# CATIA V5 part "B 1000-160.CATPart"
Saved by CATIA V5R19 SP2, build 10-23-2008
Part number: B 1000-160
Bounding box of the stored display mesh (mm): x -24.865 to 24.865, y -24.997 to 24.997, z 0 to 415
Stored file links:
  C:\Users\Bora\Desktop\3D Katı model\B serisi\B 1000\B 1000-160.CATPart
  C:\Program Files\Dassault Systemes\B19\intel_a\reffiles\standard\MetricThickPitch.txt
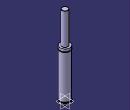
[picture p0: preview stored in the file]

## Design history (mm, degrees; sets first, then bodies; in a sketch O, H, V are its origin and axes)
Body1 (main body)
  Sketch1 on yz-plane, origin (0, 0, 0), H (0, 1, 0), V (0, 0, 1)
    point P1 (25, 239.5)
    point P2 (25, 235.5)
    point P3 (25, 239.5)
    point P6 (25, 235.5)
    point P9 (15, 414)
    point P11 (15, 414)
    arc A1 centre (25, 237.5) radius 2 from (25, 239.5) to (25, 235.5) ccw
    line L1 (25, 239.5) -> (25, 252)
    line L2 (25, 13) -> (25, 235.5)
    line L3 (21.5, 13) -> (21.5, 8)
    arc A2 centre (14, 414) radius 1 from (15, 414) to (14, 415) ccw
    line L4 (15, 414) -> (15, 252)
    line L5 (25, 0) -> (25, 8)
    line L6 (0, 0) -> (25, 0)
    line L7 (21.5, 8) -> (25, 8)
    line L8 (21.5, 13) -> (25, 13)
    line L9 (15, 252) -> (25, 252)
    line L10 (14, 415) -> (0, 415)
    point P15 (0, 415)
    horizontal: L6 H, L7 H, L8 H, L9 H
    coincidence: P15 V, P1 P3, P2 P6, P9 P11
    tangency: L10 A2
  Shaft1: profile Sketch1, axis Sketch1.V, angle 360
  Sketch2 on face of Shaft1 from Sketch1.L6, origin (0, 0, 0), H (1, 0, 0), V (0, -1, 0)
    point P1 (10, 0)
    distance P1 V = 10
  Hole1: placed by Sketch2, at (10, 0, 0) direction (0, 0, 1), diameter 6.647, depth 13, threaded "M8", thread diameter 8, thread depth 13, pitch 1.25
  CircPattern1: of Hole1, instances 2, angular step 180, axis from xy-plane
